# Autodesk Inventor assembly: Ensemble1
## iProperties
Shininess: 21.0
Length Units: 11269
Angle Units: 11279
Time Units: 11290
Mass Units: 11283
Length Display Precision: 3
Angle Display Precision: 2
Compacted: True
Created: 2001-12
Part Number: Ensemble1
Document SubType Name: Assemblage
Designer: pichon
Density: 0.0
Volumn: 0.0
Area: 0.0
PropertySet Name: Model Information
Control State: 0
Master: False
Checked Out: False
Author: pichon
